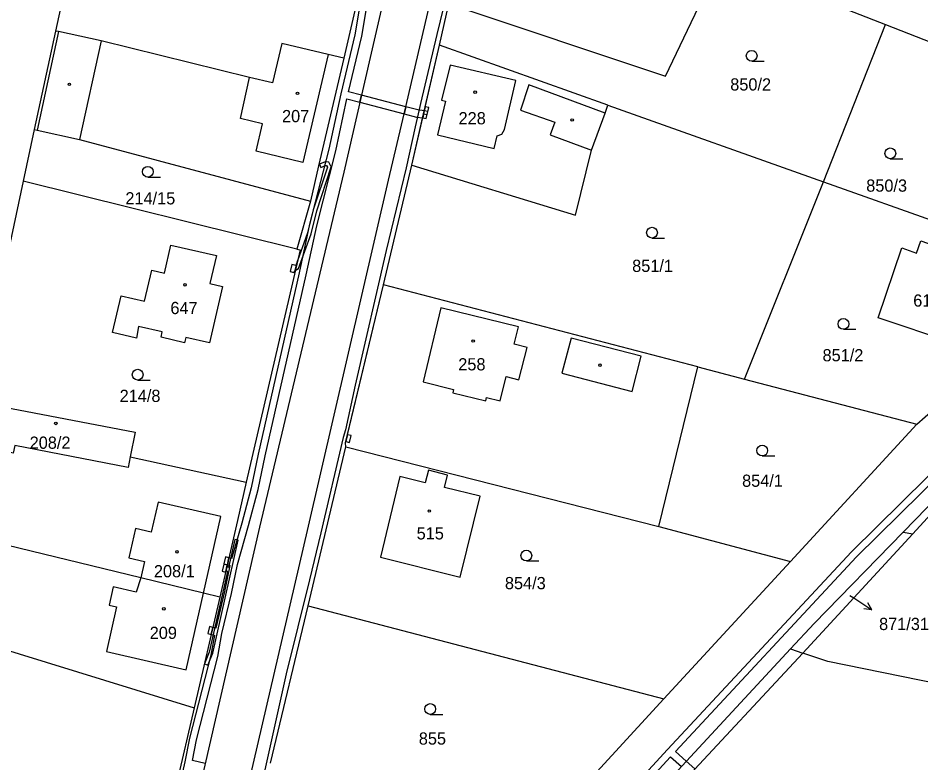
# Model space of a CAD drawing. Extents: x -776734 to -748832, y -1118122 to -976986.
# Drawn here: x -752850.8 to -752725, y -1114822 to -1114718.3 of the extents above; entities that cross this region are included whole.
import ezdxf

# ---------------------------------------------------------------- set-up
doc = ezdxf.new("R2010")
doc.units = 0
for name, color, linetype in [('KM_Hranice parcel', 7, 'Continuous'), ('KM_Parcelní čísla', 7, 'Continuous'), ('KM_Pop  PČ popisy', 7, 'Continuous'), ('KM_Vnitřní kresba', 7, 'Continuous'), ('KM_Věcná břemena k části', 7, 'Continuous'), ('KM_Značky budov', 7, 'Continuous'), ('KM_Značky kultur', 7, 'Continuous')]:
    doc.layers.add(name, color=color, linetype=linetype)

msp = doc.modelspace()

# ---------------------------------------------------------------- linework, layer by layer
at = {"layer": 'KM_Hranice parcel'}
for p, q in [((-752841.41, -1114701.06), (-752845.55, -1114720.08)), ((-752802.31, -1114710.63), (-752805.39, -1114723.86)), ((-752743.99, -1114713.66), (-752729.9, -1114719.17)), ((-752792.05, -1114722.04), (-752790.75, -1114716.31)), ((-752738.55, -1114741.07), (-752729.9, -1114719.17)), ((-752845.55, -1114720.08), (-752848.53, -1114733.8)), ((-752795.92, -1114738.75), (-752792.05, -1114722.04)), ((-752768.58, -1114730.39), (-752792.05, -1114722.04)), ((-752768.58, -1114730.39), (-752738.55, -1114741.07)), ((-752848.53, -1114733.8), (-752850.09, -1114740.98)), ((-752799.87, -1114755.43), (-752795.92, -1114738.75)), ((-752850.09, -1114740.98), (-752856.62, -1114771.71)), ((-752811.92, -1114750.47), (-752850.09, -1114740.98)), ((-752749.54, -1114768.56), (-752738.55, -1114741.07)), ((-752738.55, -1114741.07), (-752702.1, -1114754.03)), ((-752810.05, -1114743.76), (-752811.92, -1114750.47)), ((-752725.52, -1114774.82), (-752702.1, -1114754.03)), ((-752756.07, -1114766.86), (-752799.87, -1114755.43)), ((-752761.5, -1114789.11), (-752756.07, -1114766.86)), ((-752756.07, -1114766.86), (-752749.54, -1114768.56)), ((-752749.54, -1114768.56), (-752725.52, -1114774.82)), ((-752743.16, -1114793.97), (-752725.52, -1114774.82)), ((-752810.36, -1114800.13), (-752805.1, -1114778.01)), ((-752805.1, -1114778.01), (-752761.5, -1114789.11)), ((-752835.16, -1114779.4), (-752835.46, -1114780.89)), ((-752835.16, -1114779.4), (-752818.99, -1114782.92)), ((-752761.5, -1114789.11), (-752743.16, -1114793.97)), ((-752727.45, -1114789.87), (-752726.11, -1114790.11)), ((-752741.43, -1114806.72), (-752726.11, -1114790.11)), ((-752743.16, -1114793.97), (-752760.8, -1114813.12)), ((-752822.65, -1114798.92), (-752826.26, -1114814.37)), ((-752815.59, -1114822.06), (-752810.36, -1114800.13)), ((-752810.36, -1114800.13), (-752760.8, -1114813.12)), ((-752743.15, -1114806.14), (-752773.56, -1114838.95)), ((-752743.15, -1114806.14), (-752741.43, -1114806.72)), ((-752741.43, -1114806.72), (-752771.79, -1114839.34)), ((-752779.3, -1114833.2), (-752760.8, -1114813.12)), ((-752826.26, -1114814.37), (-752834.25, -1114848.56))]:
    msp.add_line(p, q, dxfattribs=at)
for points in [[(-752785.56, -1114653.59), (-752802.93, -1114729.01), (-752805.4, -1114739.76), (-752817.12, -1114789.2), (-752834.89, -1114866.39), (-752854.22, -1114948.74), (-752882.92, -1115072.56), (-752893.17, -1115116.65), (-752898.67, -1115140.84), (-752901.21, -1115152.69), (-752902.77, -1115162.03), (-752904.54, -1115175.28), (-752905.59, -1115186.25), (-752907.24, -1115206.15), (-752907.97, -1115217.91), (-752910.76, -1115260.79), (-752912.73, -1115288.36)], [(-752893.27, -1115146.65), (-752892.2, -1115141.48), (-752884.4, -1115107.23), (-752882.98, -1115101.01), (-752882.52, -1115099.06), (-752878.08, -1115079.92), (-752848.33, -1114951.79), (-752828.79, -1114868.65), (-752810.45, -1114789.66), (-752799.15, -1114740.86), (-752796.77, -1114730.63), (-752779.02, -1114654.54)], [(-752790.75, -1114716.31), (-752760.56, -1114726.35), (-752752.87, -1114710.19)], [(-752729.9, -1114719.17), (-752724.55, -1114721.26), (-752721.87, -1114722.34), (-752718.18, -1114724.07)], [(-752805.39, -1114723.86), (-752807.57, -1114723.34), (-752814.01, -1114721.83), (-752815.33, -1114727.31), (-752818.52, -1114726.55), (-752839.19, -1114721.43), (-752845.15, -1114720.16), (-752845.55, -1114720.08)], [(-752805.39, -1114723.86), (-752808.9, -1114738.88), (-752810.05, -1114743.76)], [(-752795.92, -1114738.75), (-752773.09, -1114745.72), (-752770.88, -1114736.67), (-752768.99, -1114731.51), (-752768.58, -1114730.39)], [(-752848.53, -1114733.8), (-752848.14, -1114733.88), (-752842.24, -1114735.17), (-752810.05, -1114743.76)], [(-752721.56, -1114752.36), (-752717.37, -1114753.78), (-752720.65, -1114763.47), (-752730.91, -1114760.01), (-752727.65, -1114750.3), (-752725.58, -1114751.01), (-752725, -1114749.32), (-752720.98, -1114750.68), (-752721.56, -1114752.36)], [(-752837.63, -1114762.07), (-752836.43, -1114756.97), (-752833.17, -1114757.73), (-752832.15, -1114753.38), (-752830.4, -1114753.79), (-752829.49, -1114749.9), (-752823.14, -1114751.36), (-752824.05, -1114755.26), (-752822.3, -1114755.67), (-752824.11, -1114763.53), (-752827.42, -1114762.75), (-752827.58, -1114763.5), (-752830.86, -1114762.73), (-752830.69, -1114762), (-752834, -1114761.25), (-752834.3, -1114762.87), (-752837.63, -1114762.07)], [(-752811.92, -1114750.47), (-752811.49, -1114750.57), (-752818.99, -1114782.92)], [(-752805.1, -1114778.01), (-752805.14, -1114777.44), (-752799.87, -1114755.43)], [(-752692.42, -1114759.11), (-752693.46, -1114757.91), (-752705.66, -1114768.7), (-752719.16, -1114781.38), (-752727.45, -1114789.87)], [(-752726.11, -1114790.11), (-752718.46, -1114781.81), (-752705.34, -1114770.37)], [(-752856.1, -1114771.81), (-752834.47, -1114775.95), (-752835.16, -1114779.4)], [(-752835.46, -1114780.89), (-752851.25, -1114777.8), (-752851.48, -1114778.88), (-752857.34, -1114777.56), (-752857.84, -1114777.47)], [(-752786.41, -1114784.89), (-752791.38, -1114783.68), (-752790.93, -1114781.94), (-752793.58, -1114781.24), (-752794.06, -1114783.01), (-752797.57, -1114782.14), (-752800.27, -1114793.36), (-752789.18, -1114796.17), (-752786.41, -1114784.89)], [(-752818.99, -1114782.92), (-752820.22, -1114788.26), (-752822.65, -1114798.92)], [(-752727.45, -1114789.87), (-752739.86, -1114802.59), (-752743.15, -1114806.14)], [(-752822.65, -1114798.92), (-752824.96, -1114798.36), (-752833.67, -1114796.25), (-752854.14, -1114791.29)], [(-752865.25, -1114812.44), (-752856.38, -1114814.7), (-752855.06, -1114805.49), (-752826.26, -1114814.37)], [(-752685.29, -1114818.2), (-752704.89, -1114814.64), (-752737.94, -1114807.89), (-752741.43, -1114806.72)]]:
    msp.add_lwpolyline(points, dxfattribs=at)
at = {"layer": 'KM_Pop  PČ popisy'}
for p, q in [((-752734.87, -1114798.7), (-752734.32, -1114799.05)), ((-752734.32, -1114799.05), (-752731.803, -1114800.684)), ((-752731.803, -1114800.684), (-752732.37, -1114799.719)), ((-752731.803, -1114800.684), (-752732.916, -1114800.559))]:
    msp.add_line(p, q, dxfattribs=at)
at = {"layer": 'KM_Vnitřní kresba'}
for p, q in [((-752845.15, -1114720.16), (-752848.14, -1114733.88)), ((-752839.19, -1114721.43), (-752842.24, -1114735.17)), ((-752807.57, -1114723.34), (-752811.12, -1114738.4)), ((-752790.59, -1114724.83), (-752791.79, -1114729.72)), ((-752781.44, -1114726.99), (-752790.59, -1114724.83)), ((-752819.8, -1114732.27), (-752818.52, -1114726.55)), ((-752783, -1114733.81), (-752781.44, -1114726.99)), ((-752779.61, -1114727.58), (-752780.79, -1114731.1)), ((-752768.99, -1114731.51), (-752779.61, -1114727.58)), ((-752791.21, -1114729.86), (-752792.34, -1114734.52)), ((-752791.79, -1114729.72), (-752791.21, -1114729.86)), ((-752780.79, -1114731.1), (-752775.99, -1114732.8)), ((-752816.7, -1114733.01), (-752819.8, -1114732.27)), ((-752817.62, -1114736.8), (-752816.7, -1114733.01)), ((-752775.99, -1114732.8), (-752776.63, -1114734.55)), ((-752792.34, -1114734.52), (-752784.45, -1114736.43)), ((-752784.03, -1114734.7), (-752783.39, -1114734.43)), ((-752783.39, -1114734.43), (-752783, -1114733.81)), ((-752776.63, -1114734.55), (-752770.88, -1114736.67)), ((-752784.45, -1114736.43), (-752784.03, -1114734.7)), ((-752811.12, -1114738.4), (-752817.62, -1114736.8)), ((-752791.89, -1114758.65), (-752794.35, -1114768.96)), ((-752781.06, -1114761.28), (-752791.89, -1114758.65)), ((-752781.66, -1114763.7), (-752781.06, -1114761.28)), ((-752773.71, -1114762.88), (-752775, -1114767.75)), ((-752763.95, -1114765.38), (-752773.71, -1114762.88)), ((-752779.86, -1114764.15), (-752781.66, -1114763.7)), ((-752780.98, -1114768.66), (-752779.86, -1114764.15)), ((-752765.21, -1114770.27), (-752763.95, -1114765.38)), ((-752783.61, -1114771.6), (-752782.77, -1114768.22)), ((-752782.77, -1114768.22), (-752780.98, -1114768.66)), ((-752775, -1114767.75), (-752765.21, -1114770.27)), ((-752794.35, -1114768.96), (-752790.09, -1114770.01)), ((-752790.09, -1114770.01), (-752790.21, -1114770.47)), ((-752790.21, -1114770.47), (-752785.61, -1114771.57)), ((-752785.61, -1114771.57), (-752785.5, -1114771.14)), ((-752785.5, -1114771.14), (-752783.61, -1114771.6)), ((-752831.27, -1114785.7), (-752832.22, -1114789.88)), ((-752822.55, -1114787.72), (-752831.27, -1114785.7)), ((-752824.96, -1114798.36), (-752822.55, -1114787.72)), ((-752834.4, -1114789.39), (-752835.35, -1114793.47)), ((-752832.22, -1114789.88), (-752834.4, -1114789.39)), ((-752835.35, -1114793.47), (-752833.15, -1114793.97)), ((-752833.15, -1114793.97), (-752833.67, -1114796.25)), ((-752833.67, -1114796.25), (-752834.31, -1114798.26)), ((-752837.53, -1114797.52), (-752838.11, -1114800.04)), ((-752834.31, -1114798.26), (-752837.53, -1114797.52)), ((-752827.38, -1114809.06), (-752824.96, -1114798.36)), ((-752837.09, -1114800.27), (-752838.45, -1114806.53)), ((-752838.11, -1114800.04), (-752837.09, -1114800.27)), ((-752838.45, -1114806.53), (-752827.38, -1114809.06))]:
    msp.add_line(p, q, dxfattribs=at)
at = {"layer": 'KM_Věcná břemena k části'}
for points in [[(-752790.97, -1114714.62), (-752792.44, -1114720.56), (-752794.69, -1114730.17), (-752794.91, -1114730.99), (-752795.45, -1114733.42), (-752796.68, -1114739.16), (-752799.48, -1114750.67), (-752803.79, -1114769.42), (-752805.16, -1114775.61), (-752805.46, -1114776.69), (-752808.6, -1114789.97), (-752810.15, -1114796.52), (-752813.41, -1114809.62), (-752816.79, -1114824.68)], [(-752815.59, -1114822.06), (-752810.36, -1114800.13), (-752805.1, -1114778.01), (-752805.14, -1114777.44), (-752805.1, -1114777.28), (-752804.87, -1114776.31), (-752799.87, -1114755.43), (-752795.92, -1114738.75), (-752794.27, -1114731.61), (-752794.04, -1114730.64), (-752792.05, -1114722.04), (-752790.75, -1114716.31), (-752790.49, -1114715.19)], [(-752803.11, -1114716.19), (-752803.84, -1114720.59), (-752805.82, -1114728.85), (-752807.49, -1114736.52), (-752810.15, -1114746.98), (-752811.6, -1114753.75), (-752817.33, -1114779.01), (-752818.28, -1114783.72), (-752819.6, -1114788.63), (-752821.02, -1114793.58), (-752821.4, -1114793.44), (-752821.62, -1114794.42), (-752821.26, -1114794.55), (-752822.03, -1114798.17), (-752823.22, -1114803.27), (-752823.64, -1114803.15), (-752823.87, -1114804.12), (-752823.43, -1114804.25), (-752823.91, -1114807.01), (-752826.88, -1114818.6), (-752827.53, -1114821.89), (-752831.78, -1114840.57)], [(-752824.69, -1114822.1), (-752826.48, -1114821.68), (-752825.9, -1114818.82), (-752822.93, -1114807.2), (-752822.37, -1114804.01), (-752821.06, -1114798.41), (-752820.2, -1114794.37), (-752818.65, -1114788.95), (-752817.31, -1114783.95), (-752816.37, -1114779.26), (-752810.64, -1114754.02), (-752809.17, -1114747.22), (-752806.51, -1114736.75), (-752804.95, -1114729.52), (-752803.15, -1114729.99), (-752802.93, -1114729.01), (-752804.72, -1114728.54), (-752802.86, -1114720.8), (-752802.13, -1114716.4)], [(-752701.44, -1114760.92), (-752709.71, -1114768.42), (-752712.29, -1114770.59), (-752713.67, -1114771.93), (-752734.66, -1114792.64), (-752760.29, -1114820.18), (-752790.58, -1114853.11)], [(-752756.46, -1114822.87), (-752757.66, -1114821.8), (-752759.18, -1114820.45), (-752733.93, -1114793.33), (-752712.97, -1114772.65), (-752711.63, -1114771.34), (-752709.44, -1114769.49), (-752708.09, -1114770.99), (-752707.19, -1114771.99), (-752706.44, -1114771.33), (-752707.36, -1114770.3), (-752708.68, -1114768.83), (-752699.2, -1114760.29), (-752697.83, -1114761.77), (-752696.77, -1114762.9), (-752662.6, -1114799.7), (-752648.09, -1114815.4), (-752635.45, -1114829.47)], [(-752789.85, -1114853.8), (-752759.86, -1114821.19), (-752758.34, -1114822.53)]]:
    msp.add_lwpolyline(points, dxfattribs=at)
for points in [[(-752796.77, -1114730.63), (-752802.93, -1114729.01), (-752803.15, -1114729.99), (-752796.99, -1114731.61)], [(-752794.4, -1114732.17), (-752794.17, -1114731.2), (-752795.07, -1114731.08), (-752796.77, -1114730.63), (-752796.99, -1114731.61), (-752795.27, -1114732.06)], [(-752794.04, -1114730.64), (-752794.27, -1114731.61), (-752793.78, -1114731.72), (-752793.55, -1114730.75)], [(-752794.17, -1114731.2), (-752794.4, -1114732.17), (-752793.91, -1114732.28), (-752793.68, -1114731.31)], [(-752811.7, -1114753.15), (-752809.96, -1114748.34), (-752809.16, -1114745.13), (-752807.14, -1114739.02), (-752807.46, -1114738.36), (-752807.98, -1114738.29), (-752808.79, -1114738.61), (-752808.61, -1114739.07), (-752807.92, -1114738.81), (-752807.8, -1114738.82), (-752807.68, -1114739.06), (-752809.64, -1114744.99), (-752810.44, -1114748.2), (-752811.84, -1114752.07), (-752812.16, -1114753.45)], [(-752812.85, -1114753.58), (-752812.36, -1114753.7), (-752812.33, -1114753.56), (-752812.16, -1114753.45), (-752811.84, -1114752.07), (-752812.08, -1114752.74), (-752812.62, -1114752.61)], [(-752804.38, -1114776.42), (-752804.87, -1114776.31), (-752805.1, -1114777.28), (-752804.62, -1114777.4)], [(-752821.59, -1114795.36), (-752822.34, -1114798.67), (-752824.14, -1114806.6), (-752824.82, -1114808.21), (-752824.34, -1114808.41), (-752823.66, -1114806.75), (-752821.92, -1114799.09), (-752820.09, -1114791), (-752820.58, -1114790.89), (-752821.47, -1114794.83), (-752821.68, -1114794.68), (-752821.8, -1114795.2)], [(-752821.62, -1114794.42), (-752821.4, -1114793.44), (-752821.89, -1114793.33), (-752822.11, -1114794.31)], [(-752821.8, -1114795.2), (-752821.68, -1114794.68), (-752821.64, -1114794.47), (-752822.12, -1114794.35), (-752822.35, -1114795.33), (-752821.86, -1114795.45)], [(-752823.87, -1114804.12), (-752823.64, -1114803.15), (-752824.13, -1114803.04), (-752824.35, -1114804.01)]]:
    msp.add_lwpolyline(points, close=True, dxfattribs=at)
at = {"layer": 'KM_Značky budov'}
for centre in [(-752843.6368, -1114727.4992), (-752811.8368, -1114728.7592), (-752787.0868, -1114728.5992), (-752773.5668, -1114732.4692), (-752827.5168, -1114755.4392), (-752787.3668, -1114763.2592), (-752769.6968, -1114766.6192), (-752845.5168, -1114774.7392), (-752793.4768, -1114786.9392), (-752828.6368, -1114792.6192), (-752830.4668, -1114800.5592)]:
    msp.add_circle(centre, 0.175, dxfattribs=at)
at = {"layer": 'KM_Značky kultur'}
for p, q in [((-752748.553, -1114724.28), (-752746.803, -1114724.28)), ((-752729.233, -1114737.87), (-752727.483, -1114737.87)), ((-752832.703, -1114740.43), (-752830.953, -1114740.43)), ((-752762.443, -1114748.92), (-752760.693, -1114748.92)), ((-752735.773, -1114761.63), (-752734.023, -1114761.63)), ((-752834.113, -1114768.7), (-752832.363, -1114768.7)), ((-752747.083, -1114779.27), (-752745.333, -1114779.27)), ((-752779.953, -1114793.9), (-752778.203, -1114793.9)), ((-752793.343, -1114815.27), (-752791.593, -1114815.27))]:
    msp.add_line(p, q, dxfattribs=at)
for centre in [(-752748.5529, -1114723.5298), (-752729.2329, -1114737.1198), (-752832.7029, -1114739.6798), (-752762.4429, -1114748.1698), (-752735.7729, -1114760.8798), (-752834.1129, -1114767.9498), (-752747.0829, -1114778.5198), (-752779.9529, -1114793.1498), (-752793.3429, -1114814.5198)]:
    msp.add_circle(centre, 0.75, dxfattribs=at)

# ---------------------------------------------------------------- texts
at = {"layer": 'KM_Parcelní čísla'}
for s, p in [('850/2', (-752751.54, -1114728.37)), ('207', (-752814, -1114732.78)), ('228', (-752789.4, -1114733.08)), ('850/3', (-752732.59, -1114742.46)), ('214/15', (-752835.83, -1114744.23)), ('851/1', (-752765.21, -1114753.64)), ('613', (-752726.04, -1114758.47)), ('647', (-752829.555, -1114759.51)), ('851/2', (-752738.68, -1114766.09)), ('258', (-752789.44, -1114767.35)), ('214/8', (-752836.63, -1114771.75)), ('208/2', (-752849.168, -1114778.27)), ('854/1', (-752749.89, -1114783.57)), ('515', (-752795.24, -1114790.9)), ('208/1', (-752831.858, -1114796.17)), ('854/3', (-752782.94, -1114797.83)), ('871/31', (-752730.8, -1114803.518)), ('209', (-752832.44, -1114804.76)), ('855', (-752794.94, -1114819.48))]:
    msp.add_text(s, height=1.7, dxfattribs=at).set_placement(p)

doc.saveas('drawing.dxf')
